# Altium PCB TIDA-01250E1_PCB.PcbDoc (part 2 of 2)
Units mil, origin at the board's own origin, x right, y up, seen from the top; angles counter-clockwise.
Board outline 2200 x 3000 mil, 2 copper layers (Top Layer, Bottom Layer), stack 62 mil thick; 78 components, 50 nets, 255 pads, 52 vias.
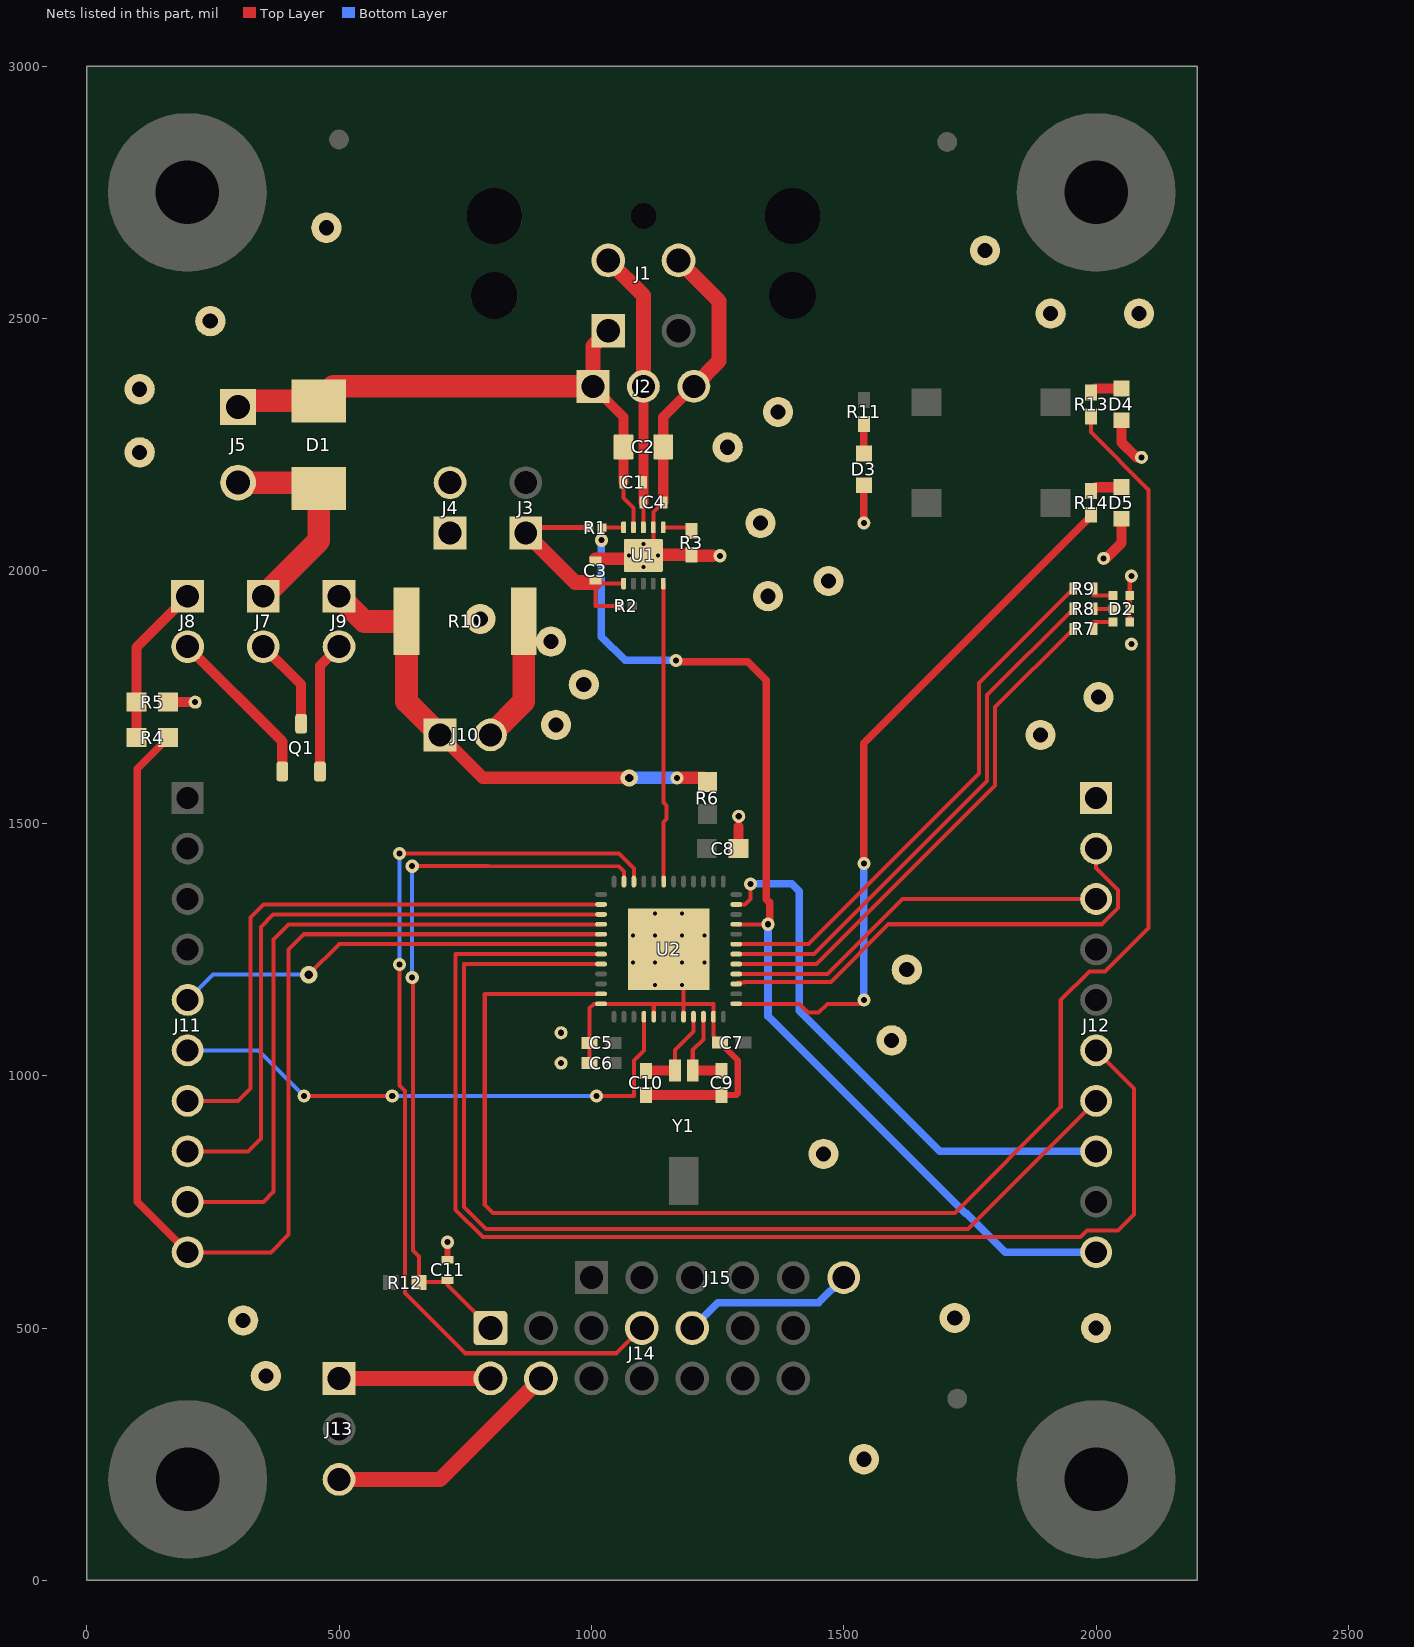
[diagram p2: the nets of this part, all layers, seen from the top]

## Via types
v1: diameter 26, hole 12, Top Layer to Bottom Layer, 30 vias
v2: diameter 19.68, hole 7.87, Top Layer to Bottom Layer, 16 vias
v3: diameter 34, hole 16, Top Layer to Bottom Layer, 6 vias

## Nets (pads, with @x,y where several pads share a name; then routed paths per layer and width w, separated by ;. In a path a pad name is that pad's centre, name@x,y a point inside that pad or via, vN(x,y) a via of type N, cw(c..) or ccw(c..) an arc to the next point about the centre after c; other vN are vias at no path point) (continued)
EN: U1.5 U2.19 | length 595.8
  Top Layer w8: U1.5@1142.52,1975.06 1142.52,1541.28 1148.5,1535.3 1148.5,1508.72 1142.52,1502.74 1142.52,1385.32 U2.19@1143.31,1384.53
GND: C2.2 C3.2 C4.2 C5.2 C6.2 C7.2 C8.2 C9.2 C10.2 C11.2 D2.4 D2.5 D2.6 D3.1 D4.1 D5.1 J1.3 J2.3 J4.1 J4.2 J10.2 J12.1 J14.9 J15.6 pad.2 pad.3 pad.4 pad.5 pad.6 pad.7 pad.8 pad.9 pad.10 pad.11 pad.12 pad.13 pad.14 pad.15 pad.16 pad.17 pad.18 pad.19 pad.20 pad.21 pad.22 pad.23 pad.24 pad.26 pad.27 pad.28 pad.29 pad.30 pad.31 pad.32 pad.33 R3.2 R5.1 R10.1 U1.7 U1.11 U2.36 U2.41 U2.44 U2.47 U2.49 | length 2923
  Top Layer w8: C6.2@996.38,1025 C5.2@996.38,1065 996.38,1133.9 1004.88,1142.4 U2.36@1019.29,1142.4 1123.62,1142.4 ; U1.11@1104.53,2032.05 1122.83,2050.35 U1.7@1122.83,2086.28 1122.83,2116.61 C4.2@1142.52,2136.3 ; U2.41@1123.62,1116.81 1123.62,1142.4 ; U2.49@1153.15,1250.67 1182.68,1250.67 1182.68,1142.4 ; U2.44@1182.68,1116.81 1182.68,1142.4 ; C7.2@1254.53,1065.67 1241.73,1078.46 U2.47@1241.73,1116.81 1241.73,1142.4 1182.68,1142.4 ; D2.4@2066.73,1898.43 D2.5@2066.73,1925 D2.6@2066.73,1951.58 2066.73,1986.73 pad.4@2070,1990 ; 1123.62,1142.4 1182.68,1142.4
  Top Layer w12: C11.2@715,638.62 v1(715,670) ; C7.2@1254.53,1065.67 1290,1030.2 1290,965 1287.05,962.05 C9.2@1258.15,962.05
  Top Layer w15: pad.6@1540,2095 D3.1@1540,2169.9
  Top Layer w20: R5.1@161.5,1740 pad.5@215,1740 ; C10.2@1108.15,962.05 C9.2@1258.15,962.05 ; C4.2@1142.52,2136.3 C2.2@1142.52,2245.67 1142.52,2305.04 J2.3@1203.16,2365.68 ; C8.2@1291.5,1450 1291.5,1493.43 ; pad.3@2015,2025 2020,2025 2050,2055 D5.1@2050,2103.5 ; D4.1@2050,2298.5 2050,2255 2080,2225 pad.2@2090,2225
  Top Layer w25: C3.2@1008.15,2024.29 1096.77,2024.29 U1.11@1103.15,2030.67 1104.53,2032.05 R3.2@1198.15,2032.05 1200.2,2030 1240,2030
  Top Layer w30: J1.3@1172.76,2615.28 1253.15,2534.88 1253.15,2415.67 J2.3@1203.16,2365.68
  Top Layer w45: J10.2@800,1675 866.14,1741.14 R10.1@866.14,1900
  Bottom Layer w15: J14.9@1200,500 1250,550 1450,550 J15.6@1500,600
  other v1: 1255,2030
  other v2: 1126.44,1179.8 1179.86,1179.8 1082.28,1223.96 1126.44,1223.96 1179.86,1223.96 1224.02,1223.96 1082.28,1277.38 1126.44,1277.38 1179.86,1277.38 1224.02,1277.38 1126.44,1321.54 1179.86,1321.54 1103.15,2008.03 1074.61,2030.67 1131.69,2030.67 1103.15,2053.31
L+: C1.1 C2.1 D1.1 J1.1 J2.1 J5.1 U1.9 | length 1155.6
  Top Layer w8: C1.1@1063.78,2176.3 1063.78,2144.1 1083.46,2124.42 U1.9@1083.46,2086.28
  Top Layer w20: J2.1@1003.16,2365.68 1063.78,2305.06 C2.1@1063.78,2245.67 C1.1@1063.78,2176.3
  Top Layer w30: J2.1@1003.16,2365.68 1003.16,2445.68 J1.1@1033.54,2476.06
  Top Layer w45: J5.1@300,2325 312.01,2337.01 D1.1@460,2337.01 488.67,2365.68 J2.1@1003.16,2365.68
LED1: R13.1 U2.35 | length 3390.4
  Top Layer w8: U2.35@1019.29,1162.09 788.8,1162.09 788.8,743.63 804.8,727.62 1720.17,727.62 1930,937.45 1930,1150 1986.63,1206.63 2017.96,1206.63 2104.13,1292.79 2104.13,2160.87 1990,2275 R13.1@1990,2306.38
LED2: R14.1 U2.1 | length 1418.3
  Top Layer w8: U2.1@1287.01,1142.4 1412.42,1142.4 1429.7,1125.13 1450.3,1125.13 1467.58,1142.4 1532.4,1142.4 v1(1540,1150)
  Top Layer w15: v1(1540,1420) 1540,1658.86 R14.1@1991.85,2110.71
  Bottom Layer w15: v1(1540,1150) v1(1540,1420)
LED_BL: R9.1 U2.7 | length 1065.2
  Top Layer w8: U2.7@1287.01,1260.51 1430.51,1260.51 1768.25,1598.25 1768.25,1778.25 R9.1@1955,1965
LED_GN: R7.1 U2.5 | length 1033.8
  Top Layer w8: U2.5@1287.01,1221.14 1446.14,1221.14 1800,1575 1800,1730 R7.1@1955,1885
LED_RD: R8.1 U2.6 | length 1051
  Top Layer w8: U2.6@1287.01,1240.83 1440.83,1240.83 1784.13,1584.13 1784.13,1754.13 R8.1@1955,1925
MISO: J12.7 U2.32 | length 2128.3
  Top Layer w8: U2.32@1019.29,1221.14 747.99,1221.14 747.99,739.53 791.65,695.87 1745.87,695.87 J12.7@2000,950
MOSI: J12.6 U2.31 | length 2536.2
  Top Layer w8: U2.31@1019.29,1240.83 730.98,1240.83 730.98,734.1 785.08,680 1968.67,680 1982.04,693.37 2043.37,693.37 2075,725 2075,975 J12.6@2000,1050
NetC1_2: C1.2 C4.1 J1.4 J2.2 U1.8 | length 557.8
  Top Layer w8: U1.8@1103.15,2086.28 C4.1@1103.15,2135.67
  Top Layer w20: C4.1@1103.15,2135.67 C1.2@1103.15,2175.67 J2.2@1103.15,2365.67
  Top Layer w30: J1.4@1033.54,2615.28 1103.16,2545.66 J2.2@1103.16,2365.68
NetC3_1: C3.1 J3.1 R1.2 R2.2 U1.1 | length 458.1
  Top Layer w8: R2.2@1055.16,1930.67 1008.15,1930.67 1008.15,1977.05 1010.14,1975.06 U1.1@1063.78,1975.06
  Top Layer w10: J3.1@870,2075 880.67,2085.67 R1.2@995.16,2085.67
  Top Layer w30: J3.1@870,2075 967.95,1977.05 C3.1@1008.15,1977.05
NetC9_1: C9.1 U2.46 Y1.1 | length 173.2
  Top Layer w8: Y1.1@1200.87,1009.92 1200.87,1050.87 1222.05,1072.05 U2.46@1222.05,1116.81 ; C9.1@1257.52,1009.92 C9.1@1258.15,1009.29
  Top Layer w20: Y1.1@1200.87,1009.92 C9.1@1257.52,1009.92
NetC10_1: C10.1 U2.45 Y1.2 | length 179.7
  Top Layer w8: C10.1@1108.15,1009.29 C10.1@1108.78,1009.92 ; Y1.2@1165.43,1009.92 1165.43,1050.43 1202.36,1087.36 U2.45@1202.36,1116.81
  Top Layer w20: C10.1@1108.78,1009.92 Y1.2@1165.43,1009.92
NetD1_2: D1.2 J5.2 J7.1 | length 423.5
  Top Layer w45: J5.2@300,2175 447.99,2175 D1.2@460,2162.99 460,2060 J7.1@350,1950
NetD2_1: D2.1 R9.2 | length 51.7
  Top Layer w8: R9.2@1995,1965 1995,1951.58 D2.1@2033.27,1951.58
NetD2_2: D2.2 R8.2 | length 38.3
  Top Layer w8: R8.2@1995,1925 D2.2@2033.27,1925
NetD2_3: D2.3 R7.2 | length 51.7
  Top Layer w8: R7.2@1995,1885 1995,1898.43 D2.3@2033.27,1898.43
NetD3_2: D3.2 R11.2 | length 58.5
  Top Layer w15: D3.2@1540,2232.89 R11.2@1540,2291.38
NetD4_2: D4.2 R13.2 | length 63.3
  Top Layer w20: R13.2@1990,2353.62 1997.87,2361.5 D4.2@2050,2361.5
NetD5_2: D5.2 R14.2 | length 63.3
  Top Layer w20: R14.2@1991.85,2157.95 1999.72,2165.83 D5.2@2051.85,2165.83
NetJ7_2: J7.2 Q1.3 | length 183.8
  Top Layer w20: J7.2@350,1850 425,1775 Q1.3@425,1697.24
NetJ8_1: J8.1 R4.2 R5.2 | length 322
  Top Layer w20: R4.2@98.5,1670 R5.2@98.5,1740 98.5,1848.5 J8.1@200,1950
NetJ8_2: J8.2 Q1.1 | length 324.9
  Top Layer w20: J8.2@200,1850 387.6,1662.4 Q1.1@387.6,1602.76
NetJ9_1: J9.1 J10.1 R6.2 R10.2 | length 980.3
  Top Layer w25: J10.1@700,1675 785,1590 v3(1075,1590) v3@1079.56,1590 ; v1(1170,1590) 1221.5,1590 R6.2@1230,1581.5
  Top Layer w45: J9.1@500,1950 550,1900 R10.2@633.86,1900 633.86,1741.14 J10.1@700,1675
  Bottom Layer w25: v3(1075,1590) v1(1170,1590)
NetJ9_2: J9.2 Q1.2 | length 262.8
  Top Layer w20: Q1.2@462.4,1602.76 462.4,1812.4 J9.2@500,1850
NetJ13_1: J13.1 J14.2 | length 300
  Top Layer w30: J13.1@500,400 J14.2@800,400
NetJ13_3: J13.3 J14.4 | length 482.8
  Top Layer w30: J13.3@500,200 700,200 J14.4@900,400
NetR3_1: R3.1 U1.6 | length 58.5
  Top Layer w8: U1.6@1142.52,2086.28 1191.16,2086.28 R3.1@1198.15,2079.29
P1.2: J12.2 U2.3 | length 954.5
  Top Layer w8: U2.3@1287.01,1181.77 1290.09,1184.86 1302.57,1184.86 1303.3,1185.58 1474.51,1185.58 1588.93,1300 2011.33,1300 2043.37,1332.04 2043.37,1367.96 2000,1411.33 J12.2@2000,1450
P1.5: J12.8 U2.11 | length 1105.7
  Top Layer w8: U2.11@1287.01,1339.25 1304.25,1339.25 1315,1350 v1(1315,1380)
  Bottom Layer w15: v1(1315,1380) 1396.82,1380 1411.63,1365.19 1411.63,1128.37 1690,850 J12.8@2000,850
P2.2: J11.7 U2.26 | length 1178.8
  Top Layer w8: J11.7@200,950 300,950 325,975 325,1313.5 350.75,1339.25 U2.26@1019.29,1339.25
P2.4: J11.6 U2.40 | length 1087.4
  Top Layer w8: v1(430.54,959.46) v1(605.54,959.46) ; v1(1010.54,959.46) 1084.46,959.46 1084.46,1029.96 1103.94,1049.43 U2.40@1103.94,1116.81
  Bottom Layer w8: J11.6@200,1050 340,1050 v1(430.54,959.46) ; v1(605.54,959.46) v1(1010.54,959.46)
P3.0: J12.3 U2.4 | length 774.5
  Top Layer w8: U2.4@1287.01,1201.46 1467.93,1201.46 1616.48,1350 J12.3@2000,1350
P3.4: J11.8 U2.27 | length 1259.8
  Top Layer w8: J11.8@200,850 320,850 345,875 345,1295 369.57,1319.57 U2.27@1019.29,1319.57
P3.5: J11.9 U2.28 | length 1340
  Top Layer w8: J11.9@200,750 350,750 370,770 370,1270 399.88,1299.88 U2.28@1019.29,1299.88
P3.7: J11.5 U2.30 | length 865.1
  Top Layer w8: v3(440,1200) 500.51,1260.51 U2.30@1019.29,1260.51
  Bottom Layer w8: J11.5@200,1150 250,1200 v3(440,1200)
PWM_FET: J11.10 R4.1 U2.29 | length 2498.2
  Top Layer w8: J11.10@200,650 365,650 400,685 400,1250 430.2,1280.2 U2.29@1019.29,1280.2
  Top Layer w15: R4.1@161.5,1670 100,1608.5 100,750 J11.10@200,650
TCK: J14.7 U2.22 | length 1916.8
  Top Layer w8: v1(620.13,1220.13) 620.13,980.05 630.41,969.77 630.41,569.59 750,450 1050,450 J14.7@1100,500 ; v1(620.13,1439.87) 1055.13,1439.87 1084.25,1410.75 U2.22@1084.25,1384.53
  Bottom Layer w8: v1(620.13,1220.13) v1(620.13,1439.87)
TDIO: C11.1 J14.1 R12.1 U2.23 | length 1458.1
  Top Layer w8: v1(645,1194.66) 646.28,1193.37 646.28,653.72 658.41,641.59 R12.1@658.41,590 659.79,591.38 715,591.38 715,585 J14.1@800,500 ; v1(645,1415) 795,1415 1054.39,1414.75 1064.57,1404.57 U2.23@1064.57,1384.53
  Bottom Layer w8: v1(645,1194.66) v1(645,1415)
WAKE: J12.10 R1.1 U1.10 U2.9 | length 2193.8
  Top Layer w8: v1@1020,2060 v1(1020,2060.91) 1020,2084.53 R1.1@1021.14,2085.67 1021.75,2086.28 U1.10@1063.78,2086.28 ; U2.9@1287.01,1299.88 1349.88,1299.88 v1(1350,1300)
  Top Layer w15: v1(1167.39,1822.69) 1165,1820.3 1309.7,1820.3 1346.79,1783.21 1346.79,1349.55 1353.31,1343.03 1353.31,1303.31 v1(1350,1300)
  Bottom Layer w15: v1(1020,2060.91) 1020,1870 1067.31,1822.69 v1(1167.39,1822.69) ; v1@1350,1290 1350,1117.65 1740.53,727.13 1742.87,727.13 1820,650 J12.10@2000,650
pads on no net: FID1.1 FID2.1 FID3.1 H1.1 H2.1 H3.1 H4.1 H5.0 H6.0 H7.0 H8.0 J1.2 J1.5 J1.6 J1.7 J1.8 J1.9 J12.4 J12.5 J14.3 J14.5 J14.6 J14.8 J14.10 J14.11 J14.13 J15.1 J15.4 J15.5 LBL1.0 SH-J3.0 SH-J7.0 SH-J8.0 SH-J9.0 SH-J13.0 U2.8 U2.12 U2.13 U2.14 U2.15 U2.16 U2.17 U2.33 U2.38 U2.39 U2.42 U2.43 Y1.3

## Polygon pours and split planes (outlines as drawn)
GND on Bottom Layer "BOTTOM_LAYER_GND_P000" (solid, remove dead copper, pour order 0): 10,10 10,2990 2190,2990 2190,10 10,10
GND on Top Layer "TOP_LAYER_GND_P002" (solid, remove dead copper, pour order 2): 2175,2975 0,2975 0,30 2175,30

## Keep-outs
Keep-Out Layer:
  lines w8: -4,0 ccw(c0,0) 0,-4 ; -4,0 ccw(c0,0) 0,-4 ; -4,0 -4,3000 ; -4,3000 cw(c0,3000) 0,3004 ; -4,3000 cw(c0,3000) 0,3004 ; 0,-4 2200,-4 ; 0,3004 2200,3004 ; 2200,-4 ccw(c2200,0) 2204,0 ; 2200,-4 ccw(c2200,0) 2204,0 ; 2200,3004 cw(c2200,3000) 2204,3000 ; 2200,3004 cw(c2200,3000) 2204,3000 ; 2204,0 2204,3000
  text ".Layer_Name" at 577,-858.49 h60

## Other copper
Top Layer:
  text ".Layer_Name" at 577,-858.49 h60
Bottom Layer:
  text ".Layer_Name" at 577,-858.49 h60

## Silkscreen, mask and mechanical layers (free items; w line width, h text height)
Top Overlay:
  text ".Layer_Name" at 577,-858.49 h60
Bottom Overlay:
  rectangle: 420,710 720,810
  text "'.PRJ_Number'.PCB_Rev-" at 1455,725.77 h108.27
  text ".Layer_Name" at 577,-858.49 h60
Top Paste:
  text ".Layer_Name" at 577,-858.49 h60
Bottom Paste:
  text ".Layer_Name" at 577,-858.49 h60
Top Solder:
  text ".Layer_Name" at 577,-858.49 h60
  text ".Layer_Name" at 577,-858.49 h60
Bottom Solder:
  text ".Layer_Name" at 577,-858.49 h60
Drill Guide:
  text ".Layer_Name" at 577,-858.49 h60
M1 Board Outline:
  the board outline again, w10
  text ".Layer_Name" at 577,-858.49 h60
M2 Board Dimensions:
  rectangle: 0,-275 125,-150
  rectangle: 125,-400 500,-275
  lines w7: 0,-275 1000,-275 ; 125,-400 125,-150 ; 250,-400 250,-150 ; 500,-400 500,-150 ; 750,-400 750,-150 ; 0,-400 1000,-400 1000,-150 0,-150 0,-400
  text ".Layer_Name" at 577,-858.49 h60
M3 3D STEP Top:
  text ".Layer_Name" at 577,-858.49 h60
M4 3D STEP Bottom:
  text ".Layer_Name" at 577,-858.49 h60
M5 Assembly Top:
  lines w10: -292,-930.17 6308,-930.17 ; -292,-726.83 6310,-726.83 ; -292,-523.5 -292,-1133.5 3713,-1133.5 6310,-1133.5 6310,-523.5 -291.5,-523.5 -291.5,-1133.5 1284,-1133.5 ; 2173,-1133.5 2173,-523.5 ; 3440,-726.83 3440,-523.5 ; 4280,-726.83 4280,-523.5 ; 4902,-1140 4902,-937.17
  text "COMPONENTS MARKED 'DNP' SHOULD NOT BE POPULATED." at 1153.5,-318.5 h60
  text "ASSEMBLY VARIANT:" at 1153,-434 h60
  text ".VariantName" at 2189,-434 h60
  text "PCB VIEWED FROM TOP SIDE" at -228.5,-655.67 h60
  text "BOARD #:" at 2248,-655.67 h60
  text ".PRJ_Number" at 2793.5,-655.67 h60
  text "REV:" at 3638,-655.67 h60
  text ".PCB_Rev" at 3929.5,-655.67 h60
  text "SVN REV:" at 4476,-655.67 h60
  text ".VersionControl_RevNumber" at 4982,-655.67 h60
  text "TID #:" at 2248,-859 h60
  text ".TID" at 2793.5,-859 h60
  text "PLOT NAME =" at -228.5,-1064.34 h60
  text ".plot_File_Name" at 577,-1064.34 h60
  text "GENERATED    :" at 2250,-1064.34 h60
  text ".Print_Date" at 3119.5,-1064.34 h60
  text ".Print_Time" at 3848.5,-1064.34 h60
  text "TEXAS INSTRUMENTS" at 5113,-1064.34 h60
M6 Assembly Bottom:
  lines w10: -292.5,-727.33 6309.5,-727.33 ; -290.5,-930.67 6309.5,-930.67 ; 1115.5,-1140.5 1115.5,-937.67 ; 1737.5,-727.33 1737.5,-524 ; 2577.5,-727.33 2577.5,-524 ; 3844.5,-1134 3844.5,-524 ; 4733.5,-1134 6309,-1134 6309,-524 -292.5,-524 -292.5,-1134 2304.5,-1134 6309.5,-1134 6309.5,-524
  text "COMPONENTS MARKED 'DNP' SHOULD NOT BE POPULATED." at 6102,-318 h60
  text ".VariantName" at 5058,-434 h60
  text "ASSEMBLY VARIANT:" at 6097,-434 h60
  text ".VersionControl_RevNumber" at 1035.5,-656.17 h60
  text "SVN REV:" at 1541.5,-656.17 h60
  text ".PCB_Rev" at 2088,-656.17 h60
  text "REV:" at 2379.5,-656.17 h60
  text ".PRJ_Number" at 3224,-656.17 h60
  text "BOARD #:" at 3769.5,-656.17 h60
  text "PCB VIEWED FROM BOTTOM SIDE" at 6246,-656.17 h60
  text ".TID" at 3224,-859.5 h60
  text "TID #:" at 3769.5,-859.5 h60
  text "TEXAS INSTRUMENTS" at 904.5,-1064.84 h60
  text ".Print_Time" at 2169,-1064.84 h60
  text ".Print_Date" at 2898,-1064.84 h60
  text "GENERATED    :" at 3767.5,-1064.84 h60
  text ".plot_File_Name" at 5440.5,-1064.84 h60
  text "PLOT NAME =" at 6246,-1064.84 h60
M9 Title Sheet:
  drawing of 57 lines, arcs and shapes, not listed
  text "1" at 739.84,8036.5 h70
  text "2" at 3235.5,8036.5 h70
  text "3" at 5724.84,8036.5 h70
  text "4" at 8231.51,8036.5 h70
  text "5" at 10730.5,8036.5 h70
  text "6" at 13235.5,8036.5 h70
  text "A" at -416.5,6893.5 h70
  text "A" at 14383.5,6893.5 h70
  text "B" at -416.5,4513.5 h70
  text "B" at 14383.5,4513.5 h70
  text "C" at -416.5,2138.5 h70
  text "C" at 14383.5,2138.5 h70
  text "PROJECT TITLE:" at 11343.5,277.5 h45
  text ".PRJ_Title" at 11393.5,144.17 h70
  text "DESIGNED FOR:" at 11343.5,-23.5 h45
  text ".PRJ_Customer" at 11393.5,-163.5 h70
  text "D" at -416.5,-231.5 h70
  text "D" at 14383.5,-231.5 h70
  text "FILE NAME:" at 11343.5,-323.5 h45
  text ".PCB_File_Name_No_Path" at 11393.5,-443.5 h70
  text "Texas Instruments (TI) and/or its licensors do not warrant the accuracy or completeness of this specification" at 6374,-605.34 h45
  text "ENGINEER:" at 11343.5,-613.5 h45
  text "LAYOUT BY:" at 12848.5,-613.5 h45
  text "or any information contained therein. TI and/or its licensors do not warrant that this design will meet" at 6329.01,-718 h45
  text ".PRJ_Engineer" at 11393.5,-768.49 h70
  text ".PCB_Layout" at 12899,-768.49 h70
  text "the specifications, will be suitable for your application or fit for any particular purpose, or will operate in" at 6329.01,-830.67 h45
  text ".Layer_Name" at 577,-858.49 h60
  text "ALTIUM DESIGNER VERSION:" at 12848.5,-923.5 h45
  text "an implementation. TI and/or its licensors do not warrant that the design is production worthy. You should" at 6329.01,-943.33 h45
  text "completely validate and test your design implementation to confirm the system functionality for your application." at 6374,-1056 h45
  text ".print_Scale" at 11393.5,-1056.83 h70
  text ".Application_BuildNumber" at 12899,-1056.83 h70
  text "1" at 739.84,-1263.5 h70
  text "2" at 3235.5,-1263.5 h70
  text "3" at 5724.84,-1263.5 h70
  text "4" at 8231.51,-1263.5 h70
  text "5" at 10730.5,-1263.5 h70
  text "6" at 13235.5,-1263.5 h70
M10 Fab Notes:
  drawing of 173 lines, arcs and shapes, not listed
  text "DESIGN INFORMATION" at 12378.02,6201 h60
  text "MIN. TRACK WIDTH:" at 11733.46,6021 h60
  text "8" at 12829.7,6021 h60
  text "MIL" at 12984.46,6021 h60
  text "MIN. CLEARANCE:" at 11733.46,5889 h60
  text "0.2" at 12769.7,5889 h60
  text "mm" at 12984.46,5889 h60
  text "MIN. VIA PAD SIZE:" at 11733.46,5757 h60
  text "24" at 12799.71,5757 h60
  text "MIL" at 12984.46,5757 h60
  text "0.05mm (2MIL)" at 12428.46,5615.29 h60
  text "MINIMUM ANNULAR RING" at 11404.23,5611 h60
  text "EXTERNAL" at 13136.46,5611 h60
  text "PER" at 11604.23,5493 h60
  text "IPC-D-275 CLASS 2 LEVEL C" at 11824.23,5493 h60
  text "MIL, HOLES" at 13312.46,5380.71 h60
  text "+/-" at 12920,5380 h60
  text "+/-" at 13774,5380 h60
  text "REGISTRATION TOLERANCES:" at 11404.23,5375 h60
  text "METAL" at 12604,5375 h60
  text "5" at 13180.2,5375 h60
  text "3" at 14013.2,5375 h60
  text "MIL" at 14129.46,5375 h60
  text "+/-" at 13774,5262 h60
  text "HOLE SIZE TOLERANCE (UNLESS OTHERWISE SPECIFIED):" at 11404.23,5257 h60
  text "3" at 14013.2,5257 h60
  text "MIL" at 14129.46,5257 h60
  text "MATERIAL:" at 11329.46,5047.54 h60
  text "FR-4 High Tg" at 12315.9,4907.21 h60
  text "FR-408" at 11750.46,4898.64 h60
  text "OTHER" at 13238.46,4898.64 h60
  text "X" at 12161,4895 h60
  text "62 MIL (1.6mm) +/-10%" at 12070.56,4735.92 h60
  text "THICKNESS:" at 11404.23,4731.64 h60
  text "X" at 11942.4,4731.64 h60
  text "OTHER" at 13355.46,4731.64 h60
  text "TOLERANCE:" at 11404.23,4573.64 h60
  text "X" at 12243.53,4573.64 h60
  text "ANSI IPC-6012 TYPE 3 CLASS 2" at 12430.48,4573.64 h60
  text "OTHER +/-" at 12430.46,4417.64 h60
  text "BOW & TWIST:" at 11404.23,4260.64 h60
  text "X" at 12243.53,4260.64 h60
  text "ANSI IPC-6012 TYPE 3 CLASS 2" at 12430.48,4260.64 h60
  text "OTHER +/-" at 12430.46,4102.13 h60
  text "DRILLING:" at 11329.46,3963.64 h60
  text "REFERENCE:" at 11404.23,3846.64 h60
  text "X" at 12052.46,3846.64 h60
  text "AS SHOWN" at 12239.46,3846.64 h60
  text "X" at 12953.46,3846.64 h60
  text "NC_DRILL FILES" at 13090.46,3846.64 h60
  text "PTH COPPER THICKNESS:" at 11404.23,3688.64 h60
  text "X" at 12534.46,3688.64 h60
  text "20-30 um" at 12671.46,3688.64 h60
  text "OTHER" at 13388.46,3688.64 h60
  text "BOARD FINISH:" at 11329.46,3529.64 h60
  text "SILKSCREEN:" at 11484.68,3411.64 h60
  text "X" at 12433.46,3411.64 h60
  text "TOP" at 12559.46,3411.64 h60
  text "X" at 12943.46,3411.64 h60
  text "BOTTOM" at 13070.46,3411.64 h60
  text "SILKSCREEN COLOR:" at 11484.68,3244.64 h60
  text "X" at 12432.42,3244.64 h60
  text "WHITE" at 12559.46,3244.64 h60
  text "OTHER" at 13070.46,3244.64 h60
  text "X" at 12563.42,3085.44 h60
  text "GREEN" at 12690.46,3085.44 h60
  text "OTHER" at 13308.46,3085.44 h60
  text "SOLDER RESIST COLOR:" at 11484.68,3074.64 h60
  text "X" at 12563.42,2915.44 h60
  text "MATTE" at 12690.46,2915.44 h60
  text "SEMI-GLOSS" at 13308,2914.8 h60
  text "IMMERSION GOLD (ENIG)" at 12390.46,2726.92 h60
  text "ENEPIG" at 13728,2723.64 h60
  text "SURFACE FINISH:" at 11329.46,2722.64 h60
  text "X" at 12203.51,2722.64 h60
  text "IMM. TIN/SILVER OR EQUIV" at 11659,2565.64 h60
  text "OTHER" at 13090.46,2565.64 h60
  text "ARRAY/PANEL:" at 11329.46,2386.64 h60
  text "CUT AND TRIM PER M1 BOARD OUTLINE" at 12390.46,2382.35 h60
  text "N.C. ROUTE" at 12390.46,2230.64 h60
  text "X" at 13069.46,2230.64 h60
  text "V. SCORE" at 13256.46,2230.64 h60
  text "CERTIFICATION:" at 11329.46,2093.64 h60
  text "MATERIALS AND WORKMANSHIP FOR ALL PCBS" at 12054.46,2093.64 h60
  text "TO MEET OR EXCEED THE REQUIREMENTS OF:" at 12054.46,1995.64 h60
  text "X" at 11680.96,1859.13 h60
  text "ANSI IPC-A-600F CLASS ->" at 11819.96,1859.13 h60
  text "X" at 13459.02,1859.13 h60
  text "2" at 13577.96,1859.14 h60
  text "1" at 13262.96,1857.64 h60
  text "3" at 13931.96,1857.64 h60
  text "X" at 12495.02,1699.64 h60
  text "RoHS" at 12631.96,1699.64 h60
  text "OTHER" at 13276.36,1699.64 h60
  text "PER ORDER" at 13673.42,1699.64 h60
  text "ALL BOARDS MUST MEET OR EXCEED UL94-V0 REQUIREMENTS." at 11357,1534 h60
  text "PCB MUST BEAR THE UL94V-0 UL REGISTERED MATERIAL ID NUMBER" at 11357,1414 h60
  text "ADDITIONAL REQUIREMENTS:" at 11329.46,1240.64 h60
  text "MICROSECTION:" at 11404.23,1125.64 h60
  text "YES" at 12309.96,1125.64 h60
  text "REQUIRED" at 13171.46,969.49 h60
  text "BARE BOARD ELEC. TEST:" at 11404.23,966.64 h60
  text "NONE" at 12709.96,966.64 h60
  text "X" at 13044.46,966.64 h60
  text "PER ORDER" at 13763.46,966.64 h60
  text ".Layer_Name" at 577,-858.49 h60
M11 Gerber Information:
  lines w10: -292,-930.17 6308,-930.17 ; -292,-726.83 6310,-726.83 ; -292,-523.5 -292,-1133.5 3713,-1133.5 6310,-1133.5 6310,-523.5 -291.5,-523.5 -291.5,-1133.5 1284,-1133.5 ; 2173,-1133.5 2173,-523.5 ; 3440,-726.83 3440,-523.5 ; 4280,-726.83 4280,-523.5 ; 4902,-1140 4902,-937.17
  text "ALL ARTWORK VIEWED FROM TOP SIDE" at -228.5,-655.67 h60
  text "BOARD #:" at 2248,-655.67 h60
  text ".PRJ_Number" at 2793.5,-655.67 h60
  text "REV:" at 3638,-655.67 h60
  text ".PCB_Rev" at 3929.5,-655.67 h60
  text "SVN REV:" at 4476,-655.67 h60
  text ".VersionControl_RevNumber" at 4982,-655.67 h60
  text "LAYER NAME =" at -228.5,-858.49 h60
  text "TID #:" at 2248,-859 h60
  text ".TID" at 2793.5,-859 h60
  text "PLOT NAME =" at -228.5,-1064.34 h60
  text ".plot_File_Name" at 577,-1064.34 h60
  text "GENERATED    :" at 2250,-1064.34 h60
  text ".Print_Date" at 3119.5,-1064.34 h60
  text ".Print_Time" at 3848.5,-1064.34 h60
  text "TEXAS INSTRUMENTS" at 5113,-1064.34 h60
M12 Stackup:
  drawing of 191 lines, arcs and shapes, not listed
  text "Layer" at 9742.5,7772.5 h60
  text "Name" at 10152.41,7772.5 h60
  text "Material" at 11082.16,7772.5 h60
  text "Thickness" at 11941.92,7772.5 h60
  text "Constant" at 12591.76,7772.5 h60
  text "Board Layer Stack" at 13161.62,7772.5 h60
  text "1" at 9742.5,7652.5 h60
  text "Top Overlay" at 10152.41,7652.5 h60
  text "2" at 9742.5,7532.5 h60
  text "Top Solder" at 10152.41,7532.5 h60
  text "Solder Resist" at 11082.16,7532.5 h60
  text "0.40mil" at 11941.92,7532.5 h60
  text "3.5" at 12591.76,7532.5 h60
  text "3" at 9742.5,7412.5 h60
  text "Top Layer" at 10152.41,7412.5 h60
  text "Copper" at 11082.16,7412.5 h60
  text "1.40mil" at 11941.92,7412.5 h60
  text "4" at 9742.5,7292.5 h60
  text "Dielectric1" at 10152.41,7292.5 h60
  text "FR-4" at 11082.16,7292.5 h60
  text "59.20mil" at 11941.92,7292.5 h60
  text "4.8" at 12591.76,7292.5 h60
  text "5" at 9742.5,7172.5 h60
  text "Bottom Layer" at 10152.41,7172.5 h60
  text "Copper" at 11082.16,7172.5 h60
  text "1.40mil" at 11941.92,7172.5 h60
  text "6" at 9742.5,7052.5 h60
  text "Bottom Solder" at 10152.41,7052.5 h60
  text "Solder Resist" at 11082.16,7052.5 h60
  text "0.40mil" at 11941.92,7052.5 h60
  text "3.5" at 12591.76,7052.5 h60
  text "7" at 9742.5,6932.5 h60
  text "Bottom Overlay" at 10152.41,6932.5 h60
  text ".Layer_Name" at 577,-858.49 h60
M13 Component Bodies Top:
  text ".Layer_Name" at 577,-858.49 h60
M14 Component Bodies Bottom:
  text ".Layer_Name" at 577,-858.49 h60
M15 Courtyards Top:
  text ".Layer_Name" at 577,-858.49 h60
M16 Courtyards Bottom:
  text ".Layer_Name" at 577,-858.49 h60
Drill Drawing:
  circle w10: c4883.73,2204.58 r16.58
  circle w10: c4883.73,2204.58 r27.63
  circle w10: c4883.73,1582.91 r27.63
  lines w10: 4856.1,1693.43 4869.91,1693.43 4869.91,1679.61 4897.54,1679.61 4897.54,1693.43 4911.36,1693.43 4911.36,1721.06 4897.54,1721.06 4897.54,1734.87 4869.91,1734.87 4869.91,1721.06 4856.1,1721.06 4856.1,1693.43 ; 4856.1,1803.95 4883.73,1817.76 4911.36,1803.95 4897.54,1831.58 4911.36,1859.21 4883.73,1845.39 4856.1,1859.21 4869.91,1831.58 4856.1,1803.95 ; 4856.1,1928.28 4911.36,1928.28 4911.36,1983.54 4856.1,1983.54 4856.1,1928.28 ; 4856.1,2107.88 4911.36,2107.88 4883.73,2052.62 4856.1,2107.88 ; 4856.1,2328.92 4883.73,2301.29 4911.36,2328.92 4883.73,2356.55 4856.1,2328.92 ; 4856.1,2425.62 4856.1,2439.44 4869.91,2453.26 4856.1,2467.07 4856.1,2480.89 4869.91,2480.89 4883.73,2467.07 4897.54,2480.89 4911.36,2480.89 4911.36,2467.07 4897.54,2453.26 4911.36,2439.44 4911.36,2425.62 4897.54,2425.62 4883.73,2439.44 4869.91,2425.62 4856.1,2425.62 ; 4856.1,2549.96 4856.1,2563.78 4869.91,2577.59 4856.1,2591.41 4856.1,2605.22 4869.91,2605.22 4883.73,2591.41 4897.54,2605.22 4911.36,2605.22 4911.36,2591.41 4897.54,2577.59 4911.36,2563.78 4911.36,2549.96 4897.54,2549.96 4883.73,2563.78 4869.91,2549.96 4856.1,2549.96 ; 4856.1,2674.3 4883.73,2688.11 4911.36,2674.3 4897.54,2701.93 4911.36,2729.56 4883.73,2715.74 4856.1,2729.56 4869.91,2701.93 4856.1,2674.3 ; 4856.1,2853.89 4911.36,2853.89 4883.73,2798.63 4856.1,2853.89 ; 4867.15,1815 4883.73,1823.29 4900.3,1815 4892.02,1831.58 4900.3,1848.16 4883.73,1839.87 4867.15,1848.16 4875.44,1831.58 4867.15,1815 ; 4867.15,1939.34 4900.3,1939.34 4900.3,1972.49 4867.15,1972.49 4867.15,1939.34 ; 4867.15,2096.83 4900.3,2096.83 4883.73,2063.67 4867.15,2096.83 ; 4867.15,2561.01 4867.15,2569.3 4875.44,2577.59 4867.15,2585.88 4867.15,2594.17 4875.44,2594.17 4883.73,2585.88 4892.02,2594.17 4900.3,2594.17 4900.3,2585.88 4892.02,2577.59 4900.3,2569.3 4900.3,2561.01 4892.02,2561.01 4883.73,2569.3 4875.44,2561.01 4867.15,2561.01
  lines w12: 4806,1517.98 8036.06,1517.98 ; 4806,2885.66 8036.06,2885.66 ; 5143.75,1393.64 5143.75,3010 ; 5475.56,1393.64 5475.56,3010 ; 6111.66,1393.64 6111.66,3010 ; 6370.66,1393.64 6370.66,3010 ; 6745.64,1393.64 6745.64,3010 ; 7469.86,1393.64 7469.86,3010 ; 4806,1393.64 8036.06,1393.64 8036.06,3010 4806,3010 4806,1393.64
  text "Symbol" at 4880.6,2922.97 h72
  text "Quantity" at 5181.05,2922.97 h72
  text "Finished Hole Size" at 5512.86,2922.97 h72
  text "Plated" at 6148.96,2922.97 h72
  text "Hole Type" at 6407.96,2922.97 h72
  text "Drill Layer Pair" at 6782.94,2922.97 h72
  text "Hole Tolerance" at 7507.16,2922.97 h72
  text "1" at 5181.05,2798.63 h60
  text "51.18mil (1.300mm)" at 5512.86,2798.63 h60
  text "NPTH" at 6148.96,2798.63 h60
  text "Round" at 6407.96,2798.63 h60
  text "Top Layer - Bottom Layer" at 6782.94,2798.63 h60
  text "2" at 5181.05,2674.3 h60
  text "92.52mil (2.350mm)" at 5512.86,2674.3 h60
  text "NPTH" at 6148.96,2674.3 h60
  text "Round" at 6407.96,2674.3 h60
  text "Top Layer - Bottom Layer" at 6782.94,2674.3 h60
  text "2" at 5181.05,2549.96 h60
  text "110.24mil (2.800mm)" at 5512.86,2549.96 h60
  text "NPTH" at 6148.96,2549.96 h60
  text "Round" at 6407.96,2549.96 h60
  text "Top Layer - Bottom Layer" at 6782.94,2549.96 h60
  text "16" at 5181.05,2425.62 h60
  text "7.87mil (0.200mm)" at 5512.86,2425.62 h60
  text "PTH" at 6148.96,2425.62 h60
  text "Round" at 6407.96,2425.62 h60
  text "Top Layer - Bottom Layer" at 6782.94,2425.62 h60
  text "39" at 5181.05,2301.29 h60
  text "12.00mil (0.305mm)" at 5512.86,2301.29 h60
  text "PTH" at 6148.96,2301.29 h60
  text "Round" at 6407.96,2301.29 h60
  text "Top Layer - Bottom Layer" at 6782.94,2301.29 h60
  text "6" at 5181.05,2176.95 h60
  text "16.00mil (0.406mm)" at 5512.86,2176.95 h60
  text "PTH" at 6148.96,2176.95 h60
  text "Round" at 6407.96,2176.95 h60
  text "Top Layer - Bottom Layer" at 6782.94,2176.95 h60
  text "26" at 5181.05,2052.62 h60
  text "30.00mil (0.762mm)" at 5512.86,2052.62 h60
  text "PTH" at 6148.96,2052.62 h60
  text "Round" at 6407.96,2052.62 h60
  text "Top Layer - Bottom Layer" at 6782.94,2052.62 h60
  text "20" at 5181.05,1928.28 h60
  text "43.31mil (1.100mm)" at 5512.86,1928.28 h60
  text "PTH" at 6148.96,1928.28 h60
  text "Round" at 6407.96,1928.28 h60
  text "Top Layer - Bottom Layer" at 6782.94,1928.28 h60
  text "24" at 5181.05,1803.95 h60
  text "45.28mil (1.150mm)" at 5512.86,1803.95 h60
  text "PTH" at 6148.96,1803.95 h60
  text "Round" at 6407.96,1803.95 h60
  text "Top Layer - Bottom Layer" at 6782.94,1803.95 h60
  text "20" at 5181.05,1679.61 h60
  text "47.24mil (1.200mm)" at 5512.86,1679.61 h60
  text "PTH" at 6148.96,1679.61 h60
  text "Round" at 6407.96,1679.61 h60
  text "Top Layer - Bottom Layer" at 6782.94,1679.61 h60
  text "4" at 5181.05,1555.28 h60
  text "125.98mil (3.200mm)" at 5512.86,1555.28 h60
  text "PTH" at 6148.96,1555.28 h60
  text "Round" at 6407.96,1555.28 h60
  text "Top Layer - Bottom Layer" at 6782.94,1555.28 h60
  text "160 Total" at 5181.05,1430.94 h60
  text ".Layer_Name" at 577,-858.49 h60
M17 Embedded Cavity:
  text ".Layer_Name" at 577,-858.49 h60
M18 Embedded Assembly:
  text ".Layer_Name" at 577,-858.49 h60
M19 Embedded Keepout:
  text ".Layer_Name" at 577,-858.49 h60

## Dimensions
0,-400 to 1000,-400 on M2 Board Dimensions
0,0 to 0,3000 on M2 Board Dimensions
0,0 to 2200,0 on M2 Board Dimensions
